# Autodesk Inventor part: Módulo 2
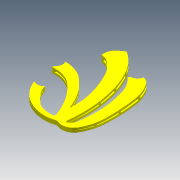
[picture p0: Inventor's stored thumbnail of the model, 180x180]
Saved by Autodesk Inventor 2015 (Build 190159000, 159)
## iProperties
Created: 2015-04
Part Number: Módulo 2
Material: Generic
Document SubType Name: Modeling
Designer: Gabriel Cabellos
Density: 1 g/cm^3
Appearance: Default
Author: Gabriel Cabellos
Sending System: SolidWorks 2008
Last Author: welington
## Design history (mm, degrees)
node "Módulo 21"
node "Extrusão9"
node "Base1"
